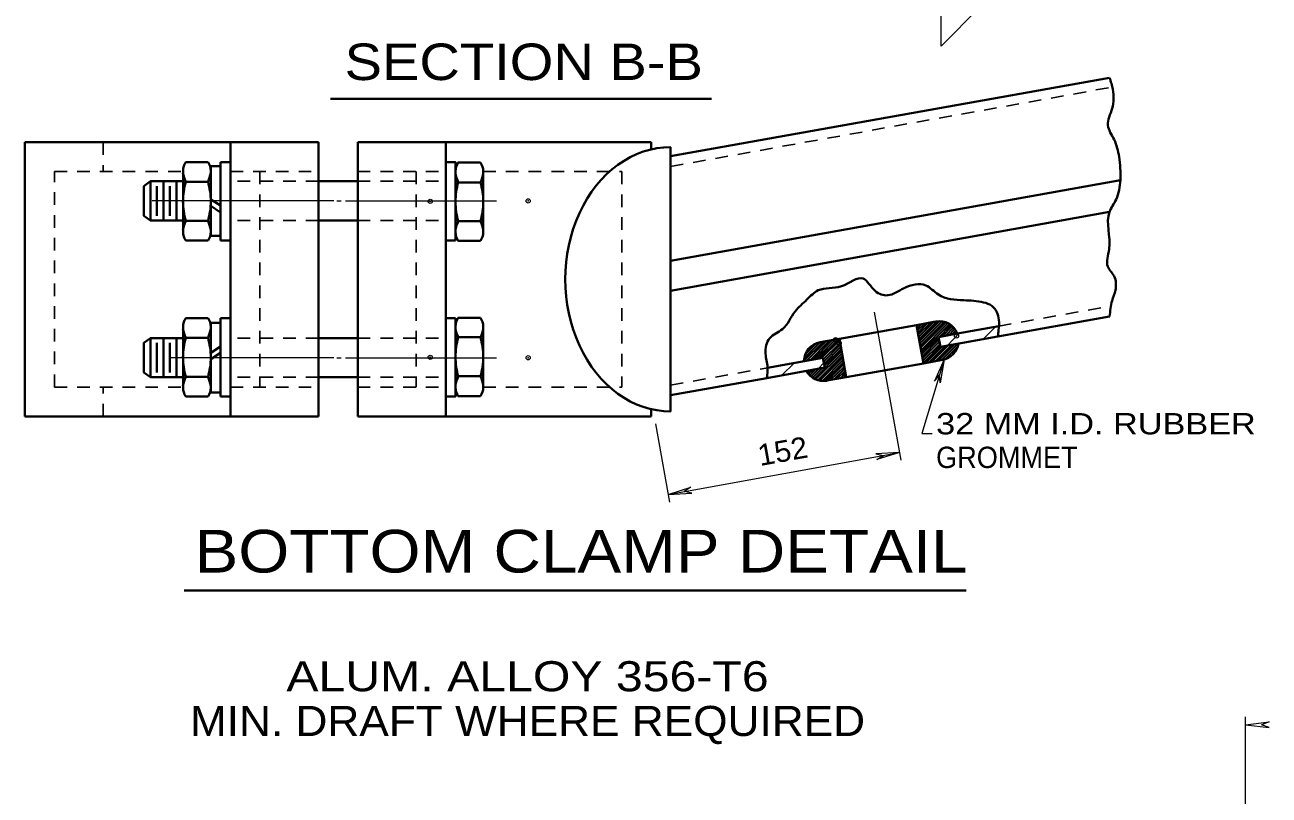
# Model space of a CAD drawing. Extents: x 312583 to 312854, y 144419 to 144597.
# Drawn here: x 312620.67 to 312664.99, y 144516.78 to 144544.19 of the extents above; entities that cross this region are included whole.
import ezdxf
from ezdxf.enums import TextEntityAlignment as Align

# ---------------------------------------------------------------- set-up
doc = ezdxf.new("R2010")
doc.units = 0
doc.header["$LTSCALE"] = 0.3
doc.header["$PDMODE"] = 32
doc.header["$PDSIZE"] = 0.15
doc.linetypes.add('SHORT_DASHED', pattern=[2.7, 1.5, -1.2])
doc.layers.add('1', color=7, linetype='Continuous', lineweight=13)

msp = doc.modelspace()

# ---------------------------------------------------------------- linework, layer by layer
at = {"layer": '1', "lineweight": 40}
for p, q in [((312643.6725, 144539.5092), (312659.3048, 144542.3076)), ((312631.5515, 144541.5562), (312645.1215, 144541.5562)), ((312620.6725, 144535.1316), (312620.6725, 144540.0076)), ((312627.9942, 144535.1316), (312627.9942, 144540.0076)), ((312631.1298, 144535.1316), (312631.1298, 144540.0076)), ((312632.5252, 144535.1316), (312632.5252, 144540.0076)), ((312635.6608, 144535.1316), (312635.6608, 144540.0076)), ((312642.9748, 144539.7546), (312642.9748, 144540.0076)), ((312643.6725, 144530.4319), (312643.6725, 144539.8389)), ((312627.2045, 144539.3022), (312626.4072, 144539.3022)), ((312627.6415, 144539.3022), (312627.6415, 144536.5116)), ((312627.6415, 144539.3022), (312627.9942, 144539.3022)), ((312627.9942, 144539.3022), (312627.9942, 144536.5116)), ((312636.0978, 144539.2869), (312636.8952, 144539.2869)), ((312626.3075, 144538.9956), (312626.3075, 144537.9146)), ((312627.2965, 144538.9956), (312627.2965, 144539.1642)), ((312627.2965, 144539.1642), (312627.2965, 144536.6802)), ((312627.2965, 144539.1642), (312627.6415, 144539.1642)), ((312627.2965, 144538.9956), (312627.2965, 144537.9222)), ((312636.0058, 144538.9879), (312636.0058, 144537.9069)), ((312636.9948, 144538.9802), (312636.9948, 144537.9069)), ((312624.9122, 144538.4512), (312624.9122, 144537.9146)), ((312626.3075, 144538.6199), (312625.1422, 144538.6199)), ((312625.3722, 144538.4512), (312625.3722, 144537.9146)), ((312625.6098, 144538.6199), (312625.6098, 144537.9146)), ((312625.8398, 144538.4512), (312625.8398, 144537.9146)), ((312626.0775, 144538.6199), (312626.0775, 144537.9146)), ((312627.2045, 144538.5969), (312626.4072, 144538.5969)), ((312632.5252, 144538.6199), (312631.1298, 144538.6199)), ((312636.0978, 144538.5816), (312636.8952, 144538.5816)), ((312643.6725, 144535.7909), (312659.6882, 144538.6659)), ((312624.9122, 144537.3856), (312624.9122, 144537.9222)), ((312625.3722, 144537.3856), (312625.3722, 144537.9222)), ((312625.6098, 144537.2246), (312625.6098, 144537.9222)), ((312625.8398, 144537.3856), (312625.8398, 144537.9222)), ((312626.0775, 144537.2246), (312626.0775, 144537.9222)), ((312626.3075, 144536.8182), (312626.3075, 144537.9222)), ((312627.2965, 144537.9759), (312627.6415, 144537.7536)), ((312627.2965, 144536.8182), (312627.2965, 144537.9222)), ((312636.0058, 144536.8029), (312636.0058, 144537.9069)), ((312636.9948, 144536.8106), (312636.9948, 144537.9146)), ((312627.2965, 144537.7459), (312627.6415, 144537.5159)), ((312643.6725, 144534.7252), (312659.3048, 144537.5312)), ((312626.3075, 144537.2246), (312625.1422, 144537.2246)), ((312627.1968, 144537.2092), (312626.3995, 144537.2092)), ((312632.5252, 144537.2246), (312631.1298, 144537.2246)), ((312636.1055, 144537.2016), (312636.9028, 144537.2016)), ((312627.2965, 144536.6802), (312627.2965, 144536.8182)), ((312627.2965, 144536.6802), (312627.6415, 144536.6802)), ((312627.2045, 144536.5116), (312626.4072, 144536.5116)), ((312627.6415, 144536.5116), (312627.9942, 144536.5116)), ((312636.0058, 144536.5116), (312635.6608, 144536.5116)), ((312636.0978, 144536.5039), (312636.8952, 144536.5039)), ((312620.6725, 144535.1316), (312620.6725, 144530.2556)), ((312627.9942, 144535.1316), (312627.9942, 144530.2556)), ((312631.1298, 144535.1316), (312631.1298, 144530.2556)), ((312632.5252, 144535.1316), (312632.5252, 144530.2556)), ((312635.6608, 144535.1316), (312635.6608, 144530.2556)), ((312626.3075, 144533.4449), (312626.3075, 144532.3409)), ((312627.2045, 144533.7516), (312626.4072, 144533.7516)), ((312627.2965, 144533.5829), (312627.2965, 144533.4449)), ((312627.2965, 144533.5829), (312627.6415, 144533.5829)), ((312627.2965, 144531.1066), (312627.2965, 144533.5829)), ((312627.2965, 144533.4449), (312627.2965, 144532.3409)), ((312627.6415, 144533.7516), (312627.9942, 144533.7516)), ((312627.6415, 144530.9609), (312627.6415, 144533.7516)), ((312627.9942, 144530.9609), (312627.9942, 144533.7516)), ((312636.0058, 144533.7516), (312635.6608, 144533.7516)), ((312635.6608, 144533.7516), (312635.6608, 144530.9609)), ((312636.0058, 144533.4602), (312636.0058, 144532.3562)), ((312636.0978, 144533.7669), (312636.8952, 144533.7669)), ((312636.9948, 144533.4602), (312636.9948, 144532.3562)), ((312649.6832, 144533.0156), (312652.4278, 144533.5062)), ((312652.4278, 144533.5062), (312653.1102, 144533.6289)), ((312652.4278, 144533.5062), (312652.6732, 144532.1416)), ((312653.8845, 144533.1996), (312655.3565, 144533.4679)), ((312655.3258, 144533.0999), (312659.3048, 144533.8129)), ((312626.3075, 144533.0386), (312625.1422, 144533.0386)), ((312625.6098, 144533.0386), (312625.6098, 144532.3409)), ((312626.0775, 144533.0386), (312626.0775, 144532.3409)), ((312627.1968, 144533.0539), (312626.3995, 144533.0539)), ((312632.5252, 144533.0386), (312631.1298, 144533.0386)), ((312636.1055, 144533.0692), (312636.9028, 144533.0692)), ((312649.6755, 144533.0156), (312648.9932, 144532.8929)), ((312649.6832, 144533.0156), (312649.9285, 144531.6509)), ((312653.2098, 144533.0769), (312653.8845, 144533.1996)), ((312653.2098, 144533.0769), (312653.2788, 144532.7319)), ((312653.2788, 144532.7319), (312655.3258, 144533.0999)), ((312624.9122, 144532.8776), (312624.9122, 144532.3409)), ((312625.3722, 144532.8776), (312625.3722, 144532.3409)), ((312625.8398, 144532.8776), (312625.8398, 144532.3409)), ((312627.2965, 144532.5172), (312627.6415, 144532.7472)), ((312624.9122, 144531.8119), (312624.9122, 144532.3486)), ((312625.3722, 144531.8119), (312625.3722, 144532.3486)), ((312625.6098, 144531.6509), (312625.6098, 144532.3486)), ((312625.8398, 144531.8119), (312625.8398, 144532.3486)), ((312626.0775, 144531.6509), (312626.0775, 144532.3486)), ((312626.3075, 144531.2676), (312626.3075, 144532.3486)), ((312627.2965, 144532.2872), (312627.6415, 144532.5172)), ((312627.2965, 144531.2676), (312627.2965, 144532.3409)), ((312636.0058, 144531.2829), (312636.0058, 144532.3562)), ((312636.9948, 144531.2829), (312636.9948, 144532.3639)), ((312647.1225, 144531.9882), (312649.0928, 144532.3332)), ((312649.0928, 144532.3332), (312649.1618, 144531.9959)), ((312649.9285, 144531.6509), (312652.6732, 144532.1416)), ((312653.3555, 144532.2642), (312652.6732, 144532.1416)), ((312626.3075, 144531.6509), (312625.1422, 144531.6509)), ((312627.2045, 144531.6662), (312626.4072, 144531.6662)), ((312632.5252, 144531.6509), (312631.1298, 144531.6509)), ((312636.0978, 144531.6816), (312636.8952, 144531.6816)), ((312647.0918, 144531.6202), (312649.1618, 144531.9959)), ((312649.2385, 144531.5282), (312649.9285, 144531.6509)), ((312627.2965, 144531.2676), (312627.2965, 144531.1066)), ((312643.6725, 144531.0069), (312647.0918, 144531.6202)), ((312627.2045, 144530.9609), (312626.4072, 144530.9609)), ((312627.2965, 144531.1066), (312627.6415, 144531.1066)), ((312627.6415, 144530.9609), (312627.9942, 144530.9609)), ((312636.0978, 144530.9762), (312636.8952, 144530.9762)), ((312642.9748, 144530.5086), (312642.9748, 144530.2556)), ((312626.3458, 144524.0609), (312654.1977, 144524.0609))]:
    msp.add_line(p, q, dxfattribs=at)
at = {"layer": '1', "linetype": 'SHORT_DASHED', "lineweight": 25}
for p, q in [((312643.6725, 144539.1489), (312659.3355, 144541.9626)), ((312623.4632, 144540.0076), (312623.4632, 144538.9649)), ((312621.7228, 144538.9649), (312626.3075, 144538.9649)), ((312621.7228, 144531.2982), (312621.7228, 144538.9649)), ((312627.9942, 144538.9649), (312631.1298, 144538.9649)), ((312629.0368, 144538.9649), (312629.0368, 144531.2982)), ((312632.5252, 144538.9649), (312635.6608, 144538.9649)), ((312634.6105, 144538.9649), (312634.6105, 144531.2982)), ((312636.9948, 144538.9649), (312641.9322, 144538.9649)), ((312641.9322, 144538.9649), (312641.9322, 144531.2982)), ((312631.1298, 144538.6199), (312627.9942, 144538.6199)), ((312632.5252, 144538.6199), (312635.6608, 144538.6199)), ((312631.1298, 144537.2246), (312627.9942, 144537.2246)), ((312632.5252, 144537.2246), (312635.6608, 144537.2246)), ((312655.3565, 144533.4679), (312659.2435, 144534.1656)), ((312631.1298, 144533.0386), (312627.9942, 144533.0386)), ((312632.5252, 144533.0386), (312635.6608, 144533.0386)), ((312631.1298, 144531.6509), (312627.9942, 144531.6509)), ((312632.5252, 144531.6509), (312635.6608, 144531.6509)), ((312643.6725, 144531.3672), (312647.1302, 144531.9882)), ((312621.7228, 144531.2982), (312626.3075, 144531.2982)), ((312623.4632, 144530.2556), (312623.4632, 144531.2982)), ((312627.9942, 144531.2982), (312631.1298, 144531.2982)), ((312632.5252, 144531.2982), (312635.6608, 144531.2982)), ((312636.9948, 144531.2982), (312641.9322, 144531.2982))]:
    msp.add_line(p, q, dxfattribs=at)
at = {"layer": '1'}
for p, q in [((312631.6742, 144537.9222), (312625.2112, 144537.9222)), ((312631.7815, 144537.9222), (312631.9425, 144537.9222)), ((312632.0958, 144537.9222), (312637.4702, 144537.9222)), ((312650.9175, 144533.9662), (312651.8682, 144528.6916)), ((312654.7968, 144533.0002), (312655.2415, 144533.4449)), ((312653.5165, 144532.7702), (312653.9535, 144533.2149)), ((312631.6742, 144532.3409), (312625.8015, 144532.3409)), ((312631.7815, 144532.3409), (312631.9425, 144532.3409)), ((312632.0958, 144532.3409), (312637.4702, 144532.3409)), ((312647.6362, 144531.7199), (312648.0732, 144532.1492)), ((312648.9242, 144531.9499), (312649.1312, 144532.1569)), ((312653.4147, 144532.2792), (312653.0734, 144531.5043)), ((312653.4147, 144532.2792), (312653.2705, 144531.4434)), ((312653.0734, 144531.5043), (312653.2489, 144531.7339)), ((312653.2705, 144531.4434), (312653.2489, 144531.7339)), ((312643.1358, 144529.9949), (312643.6342, 144527.2042)), ((312643.5882, 144527.4802), (312651.8222, 144528.9676)), ((312651.8222, 144528.9676), (312650.9788, 144528.9216)), ((312650.9788, 144528.9216), (312651.2548, 144528.8679)), ((312651.8222, 144528.9676), (312651.0095, 144528.7146)), ((312651.0095, 144528.7146), (312651.2548, 144528.8679)), ((312643.5882, 144527.4802), (312644.3932, 144527.7332)), ((312644.3932, 144527.7332), (312644.1478, 144527.5799)), ((312643.5882, 144527.4802), (312644.4315, 144527.5262)), ((312644.4315, 144527.5262), (312644.1478, 144527.5799)), ((312664.151, 144513.9841), (312664.151, 144519.5578)), ((312664.151, 144519.2818), (312664.9867, 144519.3891)), ((312664.151, 144519.2818), (312664.9867, 144519.1821)), ((312664.9867, 144519.3891), (312664.7183, 144519.2818)), ((312664.9867, 144519.1821), (312664.7183, 144519.2818))]:
    msp.add_line(p, q, dxfattribs=at)
at = {"layer": '1', "lineweight": 35}
for p, q in [((312652.4355, 144533.4602), (312652.4968, 144533.5216)), ((312652.4508, 144533.3836), (312652.6118, 144533.5369)), ((312652.4585, 144533.3069), (312652.7192, 144533.5599)), ((312652.4738, 144533.2302), (312652.8265, 144533.5829)), ((312652.4892, 144533.1536), (312652.9415, 144533.5982)), ((312652.5045, 144533.0769), (312653.0488, 144533.6212)), ((312652.5198, 144533.0002), (312653.1562, 144533.6366)), ((312652.5275, 144532.9236), (312653.2482, 144533.6442)), ((312652.5428, 144532.8469), (312653.3325, 144533.6289)), ((312652.5582, 144532.7626), (312653.4092, 144533.6212)), ((312652.5735, 144532.6936), (312653.4782, 144533.5982)), ((312652.5888, 144532.6092), (312653.5395, 144533.5676)), ((312652.6042, 144532.5402), (312653.6008, 144533.5369)), ((312653.2328, 144533.0769), (312653.6545, 144533.4986)), ((312648.8475, 144532.2949), (312649.5452, 144532.9926)), ((312648.9548, 144532.3102), (312649.6525, 144533.0079)), ((312652.6118, 144532.4559), (312653.2175, 144533.0616)), ((312652.6272, 144532.3869), (312653.2252, 144532.9849)), ((312653.5625, 144533.1382), (312653.7925, 144533.3682)), ((312653.6775, 144533.1612), (312653.8308, 144533.3146)), ((312653.7848, 144533.1842), (312653.8615, 144533.2532)), ((312648.4182, 144532.2336), (312649.1005, 144532.9082)), ((312648.4412, 144532.3409), (312648.9932, 144532.8929)), ((312648.4718, 144532.4636), (312648.8475, 144532.8392)), ((312648.5102, 144532.2336), (312649.2078, 144532.9312)), ((312648.6252, 144532.2489), (312649.3228, 144532.9466)), ((312648.7325, 144532.2719), (312649.4302, 144532.9696)), ((312648.7938, 144531.6049), (312649.7598, 144532.5709)), ((312649.0622, 144532.3332), (312649.6908, 144532.9542)), ((312649.1082, 144532.2796), (312649.7062, 144532.8776)), ((312649.1235, 144532.2106), (312649.7138, 144532.8009)), ((312649.1388, 144532.1262), (312649.7292, 144532.7242)), ((312649.1542, 144532.0572), (312649.7445, 144532.6476)), ((312652.6425, 144532.3102), (312653.2405, 144532.9082)), ((312652.6578, 144532.2336), (312653.2558, 144532.8239)), ((312652.6732, 144532.1569), (312653.2712, 144532.7549)), ((312652.7652, 144532.1569), (312653.3478, 144532.7396)), ((312652.8802, 144532.1799), (312653.4628, 144532.7626)), ((312652.9875, 144532.2029), (312653.5702, 144532.7856)), ((312653.1025, 144532.2182), (312653.6852, 144532.8009)), ((312653.2098, 144532.2412), (312653.7925, 144532.8239)), ((312653.3248, 144532.2642), (312653.8998, 144532.8392)), ((312653.4475, 144532.2949), (312653.8998, 144532.7396)), ((312653.6238, 144532.3792), (312653.8155, 144532.5709)), ((312648.8475, 144531.5742), (312649.7675, 144532.4942)), ((312648.9242, 144531.5512), (312649.7905, 144532.4176)), ((312648.9855, 144531.5282), (312649.7982, 144532.3409)), ((312649.0775, 144531.5206), (312649.8135, 144532.2642)), ((312649.1542, 144531.5129), (312649.8288, 144532.1876)), ((312649.2615, 144531.5282), (312649.8442, 144532.1109)), ((312648.5102, 144531.8656), (312648.5255, 144531.8809)), ((312648.5562, 144531.8196), (312648.6328, 144531.8962)), ((312648.5868, 144531.7659), (312648.7478, 144531.9192)), ((312648.6328, 144531.7199), (312648.8552, 144531.9422)), ((312648.6788, 144531.6739), (312648.9625, 144531.9576)), ((312648.7325, 144531.6356), (312649.0775, 144531.9806)), ((312649.3688, 144531.5512), (312649.8595, 144532.0342)), ((312649.4838, 144531.5666), (312649.8748, 144531.9576)), ((312649.5912, 144531.5896), (312649.8825, 144531.8809)), ((312649.7062, 144531.6049), (312649.8978, 144531.8042)), ((312649.8135, 144531.6279), (312649.9132, 144531.7276)), ((312649.9208, 144531.6432), (312649.9208, 144531.6509))]:
    msp.add_line(p, q, dxfattribs=at)
at = {"layer": '1'}
for points in [[(312654.6972, 144544.8299), (312653.3095, 144543.4346), (312653.3095, 144544.8299)], [(312653.4147, 144532.2792), (312652.6195, 144529.6491), (312652.9915, 144529.6491)]]:
    msp.add_lwpolyline(points, dxfattribs=at)
at = {"layer": '1', "lineweight": 40}
for points in [[(312620.6725, 144540.0076), (312627.9942, 144540.0076), (312631.1298, 144540.0076)], [(312642.9748, 144540.0076), (312635.6608, 144540.0076), (312632.5252, 144540.0076)], [(312636.0058, 144536.5116), (312636.0058, 144539.3022), (312635.6608, 144539.3022)], [(312624.9122, 144538.4512), (312625.1422, 144538.6199), (312625.1422, 144537.9146)], [(312624.9122, 144537.3856), (312625.1422, 144537.2246), (312625.1422, 144537.9222)], [(312636.0058, 144533.7516), (312636.0058, 144530.9609), (312635.6608, 144530.9609)], [(312624.9122, 144532.8776), (312625.1422, 144533.0386), (312625.1422, 144532.3409)], [(312624.9122, 144531.8119), (312625.1422, 144531.6509), (312625.1422, 144532.3486)], [(312620.6725, 144530.2556), (312627.9942, 144530.2556), (312631.1298, 144530.2556)], [(312642.9748, 144530.2556), (312635.6608, 144530.2556), (312632.5252, 144530.2556)]]:
    msp.add_lwpolyline(points, dxfattribs=at)
at = {"layer": '1', "lineweight": 35}
for points in [[(312653.3478, 144533.0999), (312653.7005, 144533.4602), (312653.7082, 144533.4602)], [(312653.4552, 144533.1229), (312653.7465, 144533.4142), (312653.7465, 144533.4142)]]:
    msp.add_lwpolyline(points, dxfattribs=at)
at = {"layer": '1', "lineweight": 40}
for centre, radius, start, end in [((312626.8783, 144538.9771), 0.574, 145.8703, 178.33743), ((312626.7202, 144538.9771), 0.574, 1.66257, 34.1297), ((312636.5821, 144538.9631), 0.574, 145.8703, 178.33743), ((312636.424, 144538.9631), 0.574, 1.66257, 34.1297), ((312627.9121, 144539.2543), 1.6437, 191.77014, 203.36365), ((312625.6864, 144539.2543), 1.6437, 336.63635, 348.22986), ((312637.6159, 144539.2403), 1.6437, 191.77014, 203.36365), ((312635.3902, 144539.2403), 1.6437, 336.63635, 348.22986), ((312629.2685, 144537.8346), 2.9664, 164.99798, 178.595), ((312624.3301, 144537.8346), 2.9664, 1.405, 15.00202), ((312638.9723, 144537.8206), 2.9664, 164.99798, 178.595), ((312634.0339, 144537.8206), 2.9664, 1.405, 15.00202), ((312629.2685, 144537.98), 2.9664, 181.405, 195.00202), ((312624.3301, 144537.98), 2.9664, 344.99798, 358.595), ((312638.9723, 144537.9661), 2.9664, 181.405, 195.00202), ((312634.0339, 144537.9661), 2.9664, 344.99798, 358.595), ((312627.9121, 144536.5604), 1.6437, 156.63635, 168.22986), ((312625.6864, 144536.5604), 1.6437, 11.77014, 23.36365), ((312637.6159, 144536.5464), 1.6437, 156.63635, 168.22986), ((312635.3902, 144536.5464), 1.6437, 11.77014, 23.36365), ((312626.8783, 144536.8375), 0.574, 181.66257, 214.1297), ((312626.7202, 144536.8375), 0.574, 325.8703, 358.33743), ((312636.5821, 144536.8236), 0.574, 181.66257, 214.1297), ((312636.424, 144536.8236), 0.574, 325.8703, 358.33743), ((312626.8783, 144533.427), 0.574, 145.8703, 178.33743), ((312626.7202, 144533.427), 0.574, 1.66257, 34.1297), ((312636.5821, 144533.4409), 0.574, 145.8703, 178.33743), ((312636.424, 144533.4409), 0.574, 1.66257, 34.1297), ((312653.2362, 144532.9498), 0.694, 20.92751, 100.40744), ((312627.9121, 144533.7042), 1.6437, 191.77014, 203.36365), ((312629.2685, 144532.2845), 2.9664, 164.99798, 178.595), ((312625.6864, 144533.7042), 1.6437, 336.63635, 348.22986), ((312624.3301, 144532.2845), 2.9664, 1.405, 15.00202), ((312637.6159, 144533.7181), 1.6437, 191.77014, 203.36365), ((312638.9723, 144532.2984), 2.9664, 164.99798, 178.595), ((312635.3902, 144533.7181), 1.6437, 336.63635, 348.22986), ((312634.0339, 144532.2984), 2.9664, 1.405, 15.00202), ((312649.1152, 144532.2079), 0.694, 99.90643, 179.34108), ((312653.2362, 144532.9498), 0.694, 279.9552, 351.41104), ((312629.2685, 144532.4299), 2.9664, 181.405, 195.00202), ((312624.3301, 144532.4299), 2.9664, 344.99798, 358.595), ((312638.9723, 144532.4439), 2.9664, 181.405, 195.00202), ((312634.0339, 144532.4439), 2.9664, 344.99798, 358.595), ((312627.9121, 144531.0103), 1.6437, 156.63635, 168.22986), ((312625.6864, 144531.0103), 1.6437, 11.77014, 23.36365), ((312637.6159, 144531.0242), 1.6437, 156.63635, 168.22986), ((312635.3902, 144531.0242), 1.6437, 11.77014, 23.36365), ((312649.1152, 144532.2079), 0.694, 208.60683, 280.45563), ((312626.8783, 144531.2874), 0.574, 181.66257, 214.1297), ((312626.7202, 144531.2874), 0.574, 325.8703, 358.33743), ((312636.5821, 144531.3014), 0.574, 181.66257, 214.1297), ((312636.424, 144531.3014), 0.574, 325.8703, 358.33743)]:
    msp.add_arc(centre, radius, start, end, dxfattribs=at)
msp.add_ellipse((312643.6739, 144535.1337), major_axis=(0, 4.7045), ratio=0.798222, start_param=6.2831853, end_param=9.424778, dxfattribs=at)
for points in [[(312659.3048, 144542.3076), (312659.4198, 144541.8936), (312659.3968, 144541.2112), (312659.2435, 144540.6132), (312659.4658, 144540.1072), (312659.6422, 144539.4939), (312659.6882, 144538.6659), (312659.5348, 144537.9682), (312659.3048, 144537.5312), (312659.2895, 144536.2049), (312659.2435, 144535.5839), (312659.4658, 144535.2389), (312659.5118, 144534.7482), (312659.3968, 144534.3726), (312659.3048, 144533.8129)], [(312647.0918, 144531.6202), (312647.1225, 144532.0112), (312647.0535, 144532.4866), (312647.1992, 144533.0386), (312647.6515, 144533.3606), (312648.1038, 144533.9892), (312648.5255, 144534.4109), (312648.9242, 144534.7406), (312649.7522, 144534.8862), (312650.5265, 144535.1622), (312650.9558, 144534.7176), (312651.4082, 144534.5642), (312651.9832, 144534.8172), (312652.7575, 144534.9169), (312653.2098, 144534.5872), (312654.1145, 144534.3879), (312654.8122, 144534.3112), (312655.1112, 144534.1886), (312655.3642, 144533.6902), (312655.3488, 144533.3222), (312655.3258, 144533.0999)]]:
    msp.add_spline(points, degree=3, dxfattribs=at)
at = {"layer": '1'}
for p in [(312635.1088, 144537.9069), (312638.5972, 144537.9222), (312649.5452, 144532.9849), (312649.5835, 144532.9466), (312653.8538, 144533.1152), (312649.6295, 144532.8929), (312649.6755, 144532.8546), (312635.1088, 144532.3562), (312638.5972, 144532.3409)]:
    msp.add_point(p, dxfattribs=at)

# ---------------------------------------------------------------- texts
for s, height, width, p in [('SECTION B-B', 1.299, 1.15, (312638.44, 144542.2232)), ('ALUM. ALLOY 356-T6', 1.07, 1.2, (312638.5742, 144520.4728)), ('MIN. DRAFT WHERE REQUIRED', 1.07, 1.1, (312638.5742, 144518.8815))]:
    msp.add_text(s, height=height, dxfattribs=dict(at, width=width)).set_placement(p, align=Align.CENTER)
for s, height, width, p in [('32 MM I.D. RUBBER', 0.76, 1.2, (312653.1261, 144529.6141)), ('GROMMET', 0.76, 0.95, (312653.1261, 144528.4171)), ('BOTTOM CLAMP DETAIL', 1.52, 1.15, (312626.7135, 144524.6974))]:
    msp.add_text(s, height=height, dxfattribs=dict(at, width=width)).set_placement(p)
at = {"layer": '1', "width": 1.05}
msp.add_text('152', height=0.76, rotation=10.213, dxfattribs=at).set_placement((312646.8531, 144528.4863))

doc.saveas('drawing.dxf')
